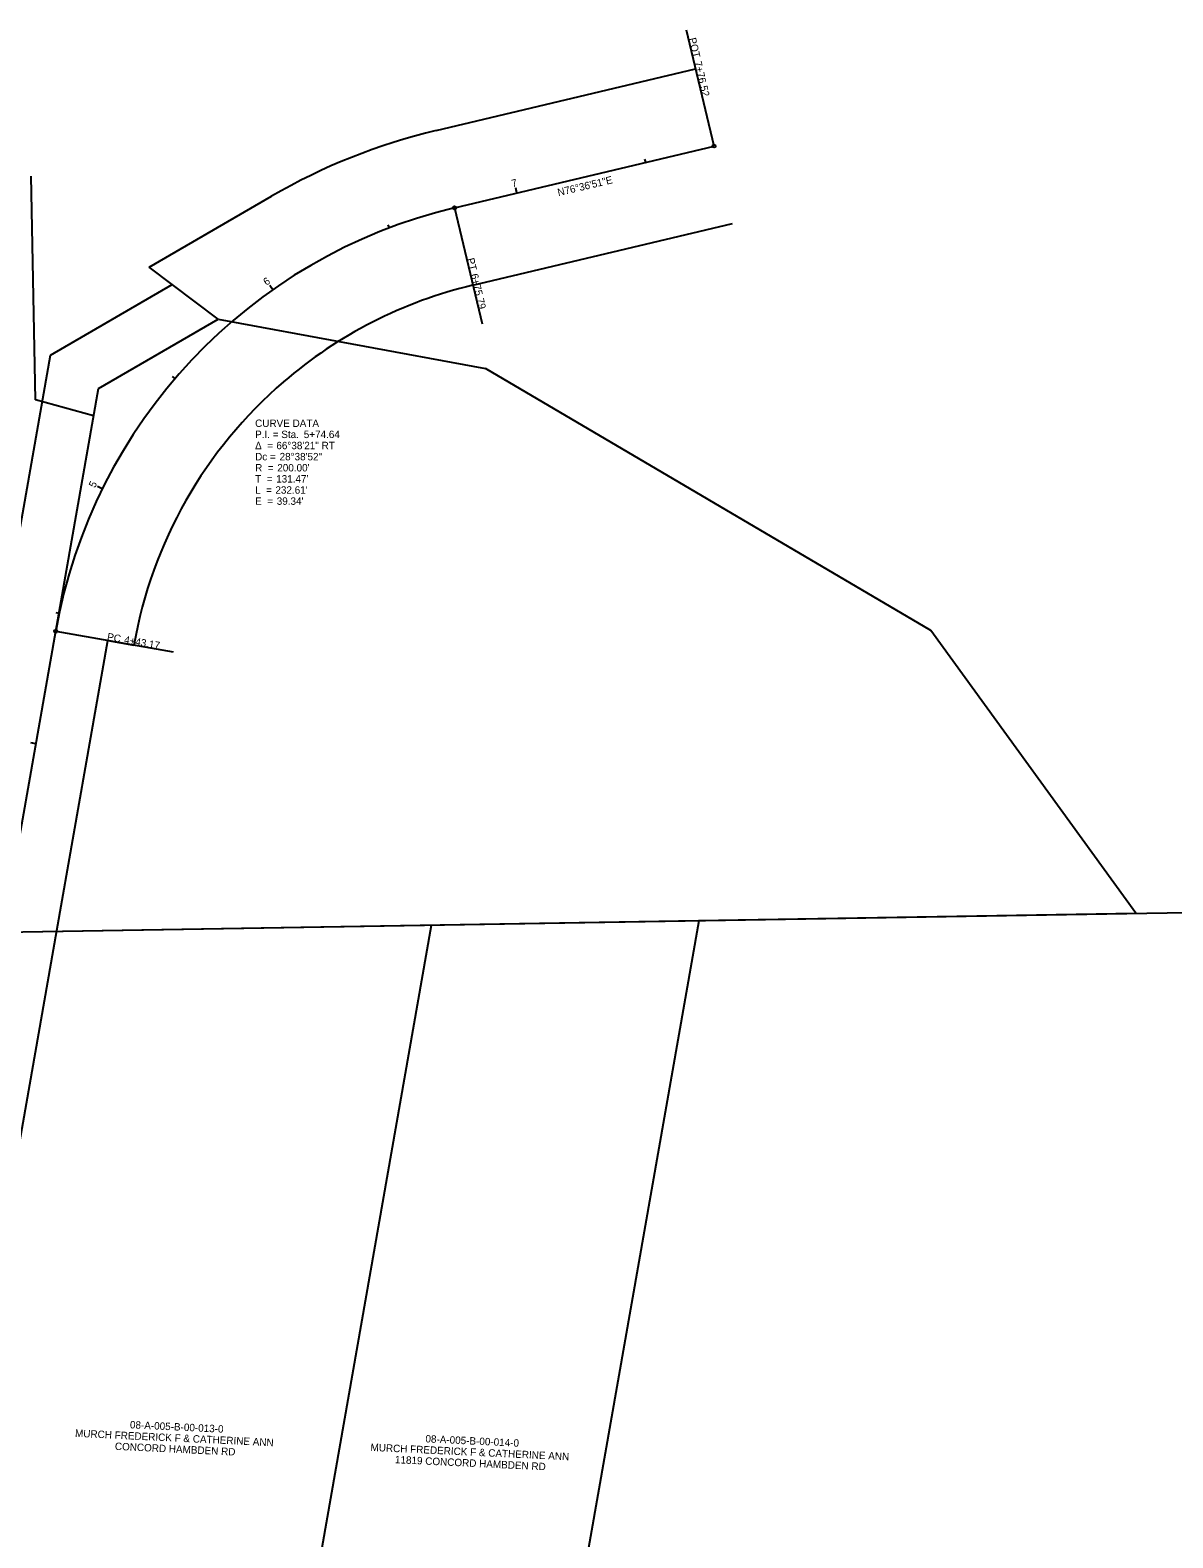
# Model space of a CAD drawing. Extents: x 2318731 to 2320621, y 732958 to 734198.
# Drawn here: x 2319469 to 2319901, y 733629 to 734198 of the extents above; entities that cross this region are included whole.
import ezdxf

# ---------------------------------------------------------------- set-up
doc = ezdxf.new("R2010")
doc.units = 0
for name, color, linetype in [('DV_X_Section_VMS_Line', 7, 'Continuous'), ('RW_X_CL_100_Bearings', 7, 'Continuous'), ('RW_X_CL_100_Cardinal_Points', 7, 'Continuous'), ('RW_X_CL_100_Stations', 7, 'Continuous'), ('RW_X_CL_500_Bearings', 7, 'Continuous'), ('RW_X_CL_500_Cardinal_Points', 7, 'Continuous'), ('RW_X_CL_500_Curve_Data', 7, 'Continuous'), ('RW_X_CL_500_Stations', 7, 'Continuous'), ('RW_X_Text', 7, 'Continuous'), ('V-SURV-IPF', 7, 'Continuous'), ('V-SURV-PARL-LINE', 7, 'Continuous'), ('V-SURV-PARL-SUBL', 7, 'Continuous'), ('V-SURV-RWAY', 7, 'Continuous')]:
    doc.layers.add(name, color=color, linetype=linetype)

msp = doc.modelspace()

# ---------------------------------------------------------------- linework, layer by layer
at = {"layer": 'DV_X_Section_VMS_Line'}
msp.add_line((2319458.71, 733857.41), (2320596.89, 733876.33), dxfattribs=at)
at = {"layer": 'RW_X_CL_100_Cardinal_Points'}
for p, q in [((2319727.36, 734154.28), (2319716.95, 734198.06)), ((2319629.37, 734130.96), (2319639.79, 734087.18)), ((2319478.69, 733971.04), (2319523.01, 733963.24))]:
    msp.add_line(p, q, dxfattribs=at)
for centre in [(2319727.36, 734154.28), (2319629.37, 734130.96), (2319478.69, 733971.04)]:
    msp.add_circle(centre, 0.6, dxfattribs=at)
at = {"layer": 'RW_X_CL_100_Stations'}
for p, q in [((2319701.57, 734148.14), (2319701.29, 734149.31)), ((2319652.93, 734136.57), (2319652.46, 734138.51)), ((2319604.74, 734123.39), (2319604.31, 734124.51)), ((2319560.68, 734100.03), (2319559.53, 734101.67)), ((2319523.77, 734066.49), (2319522.86, 734067.27)), ((2319496.31, 734024.87), (2319494.51, 734025.75)), ((2319479.99, 733977.74), (2319478.82, 733977.99)), ((2319471.22, 733928.52), (2319469.25, 733928.87))]:
    msp.add_line(p, q, dxfattribs=at)
at = {"layer": 'RW_X_CL_500_Cardinal_Points'}
for p, q in [((2319727.36, 734154.28), (2319716.95, 734198.06)), ((2319629.37, 734130.96), (2319639.79, 734087.18)), ((2319478.69, 733971.04), (2319523.01, 733963.24))]:
    msp.add_line(p, q, dxfattribs=at)
for centre in [(2319727.36, 734154.28), (2319629.37, 734130.96), (2319478.69, 733971.04)]:
    msp.add_circle(centre, 0.6, dxfattribs=at)
at = {"layer": 'RW_X_CL_500_Stations'}
for p, q in [((2319652.93, 734136.57), (2319652.65, 734137.73)), ((2319560.68, 734100.03), (2319559.99, 734101.01)), ((2319496.31, 734024.87), (2319494.51, 734025.75)), ((2319471.22, 733928.52), (2319470.03, 733928.73))]:
    msp.add_line(p, q, dxfattribs=at)
at = {"layer": 'V-SURV-IPF'}
for p, q in [((2319471.11, 734058.46), (2319469.44, 734142.91)), ((2319540.04, 734088.94), (2319522.66, 734101.98)), ((2319494.82, 734062.69), (2319540.04, 734088.94)), ((2319540.04, 734088.94), (2319641.05, 734070.34)), ((2319809.22, 733971.28), (2319641.05, 734070.34)), ((2319493, 734052.38), (2319471.11, 734058.46)), ((2319478.69, 733971.04), (2319494.82, 734062.69)), ((2319886.73, 733864.52), (2319809.22, 733971.28)), ((2319458.71, 733857.41), (2319886.73, 733864.52)), ((2319562.24, 733527.63), (2319620.71, 733860.1)), ((2319662.12, 733522.88), (2319721.73, 733861.78))]:
    msp.add_line(p, q, dxfattribs=at)
at = {"layer": 'V-SURV-PARL-LINE'}
for p, q in [((2319622.43, 734160.15), (2319720.42, 734183.47)), ((2319513.98, 734108.49), (2319560.24, 734135.33)), ((2319636.32, 734101.78), (2319734.31, 734125.09)), ((2319522.66, 734101.98), (2319513.98, 734108.49)), ((2319476.73, 734075.32), (2319522.66, 734101.98)), ((2319387.15, 733565.99), (2319476.73, 734075.32)), ((2319479.14, 733858.08), (2319498.39, 733967.57)), ((2319498.39, 733967.57), (2319508.24, 733965.84)), ((2319427.43, 733564.08), (2319479.14, 733858.08))]:
    msp.add_line(p, q, dxfattribs=at)
for radius, start, end in [(230, 103.3857, 120.1249), (170, 103.3857, 130.7201), (170, 130.7201, 170.0249)]:
    msp.add_arc((2319675.67, 733936.39), radius, start, end, dxfattribs=at)
at = {"layer": 'V-SURV-RWAY'}
for p, q in [((2319629.37, 734130.96), (2319727.36, 734154.28)), ((2319401.93, 733534.57), (2319478.69, 733971.04))]:
    msp.add_line(p, q, dxfattribs=at)
msp.add_arc((2319675.67, 733936.39), 200, 103.3857, 170.0249, dxfattribs=at)

# ---------------------------------------------------------------- texts
at = {"layer": 'RW_X_CL_100_Bearings'}
msp.add_text('N76°36\'51"E', height=2.8, rotation=13.3857, dxfattribs=at).set_placement((2319668.6, 734135.36))
at = {"layer": 'RW_X_CL_100_Cardinal_Points'}
for s, rotation, p in [('POT', 283.3857, (2319717.76, 734194.86)), ('7+76.52', 283.3857, (2319719.87, 734185.97)), ('PT', 283.3857, (2319634.01, 734111.67)), ('6+75.79', 283.3857, (2319635.42, 734105.74)), ('PC', 350.0249, (2319497.95, 733967.7)), ('4+43.17', 350.0249, (2319504.37, 733966.57))]:
    msp.add_text(s, height=2.8, rotation=rotation, dxfattribs=at).set_placement(p)
at = {"layer": 'RW_X_CL_100_Stations'}
for s, rotation, p in [('7', 13.3857, (2319651.22, 734138.73)), ('6', 35.0968, (2319558.31, 734101.48)), ('5', 63.7447, (2319493.53, 734024.99))]:
    msp.add_text(s, height=2.8, rotation=rotation, dxfattribs=at).set_placement(p)
at = {"layer": 'RW_X_CL_500_Bearings'}
msp.add_text('N76°36\'51"E', height=2.8, rotation=13.3857, dxfattribs=at).set_placement((2319668.6, 734135.36))
at = {"layer": 'RW_X_CL_500_Cardinal_Points'}
for s, rotation, p in [('POT', 283.3857, (2319717.76, 734194.86)), ('7+76.52', 283.3857, (2319719.87, 734185.97)), ('PT', 283.3857, (2319634.01, 734111.67)), ('6+75.79', 283.3857, (2319635.42, 734105.74)), ('PC', 350.0249, (2319497.95, 733967.7)), ('4+43.17', 350.0249, (2319504.37, 733966.57))]:
    msp.add_text(s, height=2.8, rotation=rotation, dxfattribs=at).set_placement(p)
at = {"layer": 'RW_X_CL_500_Curve_Data'}
for s, p in [('CURVE DATA', (2319554.03, 734048.2)), ('P.I. = Sta. ', (2319554.03, 734044)), ('5+74.64', (2319572.4, 734044)), ('Δ  = ', (2319554.03, 734039.8)), ('66°38\'21" RT', (2319562.05, 734039.8)), ('Dc = ', (2319554.03, 734035.6)), ('28°38\'52"', (2319563.27, 734035.6)), ('T  = ', (2319554.03, 734027.2)), ('R  = ', (2319554.03, 734031.4)), ("131.47'", (2319561.97, 734027.2)), ("200.00'", (2319562.4, 734031.4)), ('L  = ', (2319554.03, 734023)), ("232.61'", (2319561.68, 734023)), ('E  = ', (2319554.03, 734018.8)), ("39.34'", (2319562.19, 734018.8))]:
    msp.add_text(s, height=2.8, dxfattribs=at).set_placement(p)
at = {"layer": 'RW_X_CL_500_Stations'}
msp.add_text('5', height=2.8, rotation=63.7447, dxfattribs=at).set_placement((2319493.53, 734024.99))
at = {"layer": 'RW_X_Text'}
for s, p in [('08-A-005-B-00-013-0', (2319506.69, 733670.04)), ('MURCH FREDERICK F & CATHERINE ANN', (2319485.96, 733666.82)), ('CONCORD HAMBDEN RD', (2319501.01, 733661.9)), ('08-A-005-B-00-014-0', (2319618.3, 733664.73)), ('MURCH FREDERICK F & CATHERINE ANN', (2319597.57, 733661.51)), ('11819 CONCORD HAMBDEN RD', (2319606.79, 733656.87))]:
    msp.add_text(s, height=2.8, rotation=357.2785, dxfattribs=at).set_placement(p)
at = {"layer": 'V-SURV-PARL-SUBL'}
for s, p in [('CURVE DATA', (2319554.03, 734048.2)), ('P.I. = Sta. ', (2319554.03, 734044)), ('5+74.64', (2319572.4, 734044)), ('Δ  = ', (2319554.03, 734039.8)), ('66°38\'21" RT', (2319562.05, 734039.8)), ('Dc = ', (2319554.03, 734035.6)), ('28°38\'52"', (2319563.27, 734035.6)), ('T  = ', (2319554.03, 734027.2)), ('R  = ', (2319554.03, 734031.4)), ("131.47'", (2319561.97, 734027.2)), ("200.00'", (2319562.4, 734031.4)), ('L  = ', (2319554.03, 734023)), ("232.61'", (2319561.68, 734023)), ('E  = ', (2319554.03, 734018.8)), ("39.34'", (2319562.19, 734018.8))]:
    msp.add_text(s, height=2.8, dxfattribs=at).set_placement(p)

doc.saveas('drawing.dxf')
